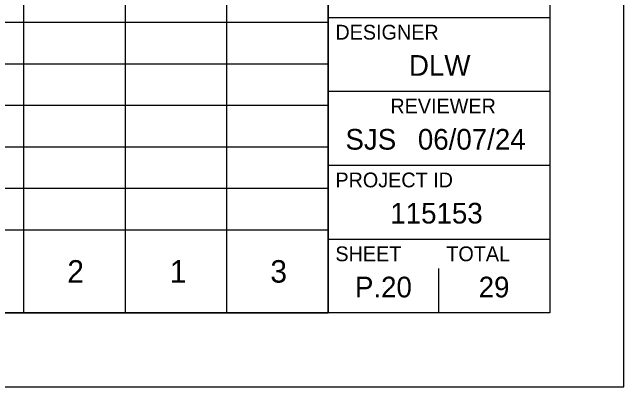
# Model space of a CAD drawing. Extents: x -0.2 to 34, y 0 to 22.
# Drawn here: x 29.865 to 34, y 0 to 2.535 of the extents above; entities that cross this region are included whole.
import ezdxf

# ---------------------------------------------------------------- set-up
doc = ezdxf.new("R2010")
doc.units = 0
for name, color, linetype in [('DV_X_Property_Line', 7, 'Continuous'), ('RW_X_CL', 7, 'Continuous'), ('SC_Scratch1', 7, 'Continuous'), ('SV_X_Mon_Cells_Found', 7, 'Continuous')]:
    doc.layers.add(name, color=color, linetype=linetype)

msp = doc.modelspace()

# ---------------------------------------------------------------- linework, layer by layer
at = {"layer": 'DV_X_Property_Line'}
for p, q in [((32, 0.5), (32, 21.5)), ((32, 2.5), (33.5, 2.5)), ((32, 2), (33.5, 2)), ((32, 1.5), (33.5, 1.5)), ((32, 1), (33.5, 1))]:
    msp.add_line(p, q, dxfattribs=at)
msp.add_lwpolyline([(1.5, 21.5), (33.5, 21.5), (33.5, 0.5), (1.5, 0.5)], close=True, dxfattribs=at)
at = {"layer": 'RW_X_CL'}
msp.add_lwpolyline([(0, 0), (34, 0), (34, 22), (0, 22)], close=True, dxfattribs=at)
at = {"layer": 'SC_Scratch1'}
for p, q in [((32.75, 0.5), (32.75, 0.8)), ((32.375, 0.675), (32.375, 0.675))]:
    msp.add_line(p, q, dxfattribs=at)
at = {"layer": 'SV_X_Mon_Cells_Found'}
for p, q in [((29.9414, 21.5), (29.9414, 0.5)), ((30.6276, 21.5), (30.6276, 0.5)), ((31.3138, 21.5), (31.3138, 0.5)), ((32, 21.5), (32, 0.5)), ((1.5, 2.4677), (32, 2.4677)), ((1.5, 2.1866), (32, 2.1866)), ((1.5, 1.9055), (32, 1.9055)), ((1.5, 1.6244), (32, 1.6244)), ((1.5, 1.3433), (32, 1.3433)), ((1.5, 1.0622), (32, 1.0622)), ((1.5, 0.5), (32, 0.5))]:
    msp.add_line(p, q, dxfattribs=at)

# ---------------------------------------------------------------- texts
at = {"layer": 'SC_Scratch1'}
for s, height, p in [('DESIGNER', 0.1, (32.05, 2.35)), ('DLW', 0.14, (32.5474, 2.105)), ('REVIEWER', 0.1, (32.4218, 1.85)), ('SJS', 0.14, (32.118, 1.605)), ('06/07/24', 0.14, (32.6078, 1.605)), ('PROJECT ID', 0.1, (32.05, 1.35)), ('115153', 0.14, (32.4215, 1.105)), ('SHEET', 0.1, (32.05, 0.85)), ('TOTAL', 0.1, (32.8, 0.85)), ('P.20', 0.14, (32.1822, 0.605)), ('29', 0.14, (33.0188, 0.605))]:
    msp.add_text(s, height=height, dxfattribs=at).set_placement(p)
at = {"layer": 'SV_X_Mon_Cells_Found'}
for s, p in [('2', (30.237, 0.705)), ('1', (30.9302, 0.705)), ('3', (31.6099, 0.705))]:
    msp.add_text(s, height=0.1521, dxfattribs=at).set_placement(p)

doc.saveas('drawing.dxf')
